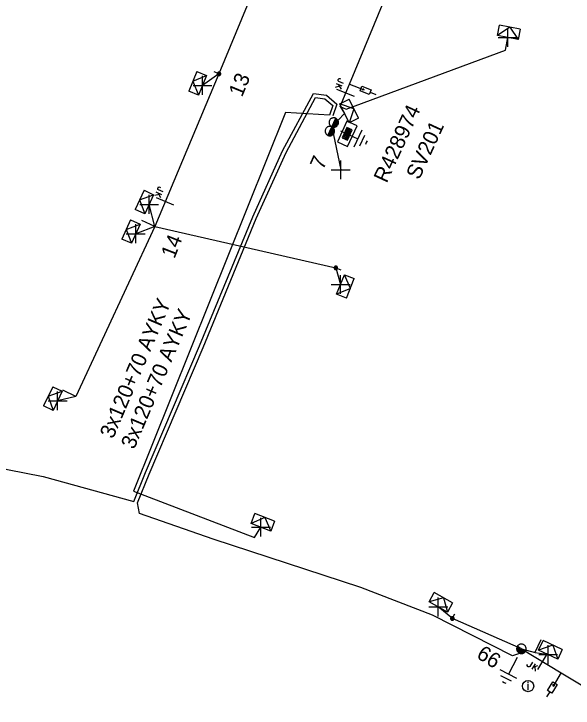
# Model space of a CAD drawing. Extents: x -540247 to -537390, y -1183890 to -1180355.
# Drawn here: x -537727.87 to -537690.84, y -1180542.13 to -1180496.15 of the extents above; entities that cross this region are included whole.
import ezdxf

# ---------------------------------------------------------------- set-up
doc = ezdxf.new("R2010")
doc.units = 0
for name, color, linetype in [('Vrstva 1', 7, 'Continuous'), ('Vrstva 10', 7, 'Continuous'), ('Vrstva 13', 7, 'Continuous'), ('Vrstva 14', 7, 'Continuous'), ('Vrstva 15', 7, 'Continuous'), ('Vrstva 16', 7, 'Continuous'), ('Vrstva 18', 7, 'Continuous'), ('Vrstva 2', 7, 'Continuous'), ('Vrstva 28', 7, 'Continuous'), ('Vrstva 29', 7, 'Continuous'), ('Vrstva 30', 7, 'Continuous'), ('Vrstva 31', 7, 'Continuous'), ('Vrstva 34', 7, 'Continuous'), ('Vrstva 36', 7, 'Continuous'), ('Vrstva 4', 7, 'Continuous'), ('Vrstva 5', 7, 'Continuous'), ('Vrstva 50', 7, 'Continuous'), ('Vrstva 52', 7, 'Continuous'), ('Vrstva 54', 7, 'Continuous'), ('Vrstva 6', 7, 'Continuous'), ('Vrstva 8', 7, 'Continuous'), ('Vrstva 9', 7, 'Continuous')]:
    doc.layers.add(name, color=color, linetype=linetype)

# ---------------------------------------------------------------- blocks, each defined once
blk = doc.blocks.new('NN440')
at = {"layer": 'Vrstva 2'}
for points in [[(0.631, -0.004), (0.627, 0.062), (0.617, 0.127), (0.6, 0.191), (0.577, 0.252), (0.547, 0.311), (0.511, 0.366), (0.469, 0.417), (0.423, 0.464), (0.371, 0.505), (0.316, 0.542), (0.257, 0.571), (0.196, 0.595), (0.132, 0.612), (0.067, 0.622), (0.001, 0.626), (-0.065, 0.622), (-0.13, 0.612), (-0.194, 0.595), (-0.255, 0.571), (-0.314, 0.542), (-0.369, 0.505), (-0.42, 0.464), (-0.467, 0.417), (-0.509, 0.366), (-0.544, 0.311), (-0.574, 0.252), (-0.598, 0.191), (-0.615, 0.127), (-0.626, 0.062), (-0.629, -0.004), (-0.626, -0.07), (-0.615, -0.135), (-0.598, -0.199), (-0.574, -0.26), (-0.544, -0.319), (-0.509, -0.374), (-0.467, -0.426), (-0.42, -0.472), (-0.369, -0.514), (-0.314, -0.55), (-0.255, -0.58), (-0.194, -0.603), (-0.13, -0.62), (-0.065, -0.631), (0.001, -0.634), (0.067, -0.631), (0.132, -0.62), (0.196, -0.603), (0.257, -0.58), (0.316, -0.55), (0.371, -0.514), (0.423, -0.472), (0.469, -0.426), (0.511, -0.374), (0.547, -0.319), (0.577, -0.26), (0.6, -0.199), (0.617, -0.135), (0.627, -0.07), (0.631, -0.004)], [(-0.631, 0), (0.629, 0)], [(-0.601, -0.177), (0.57, -0.177)], [(-0.513, -0.325), (0.501, -0.325)], [(-0.375, -0.473), (0.353, -0.473)]]:
    blk.add_lwpolyline(points, dxfattribs=at)
blk = doc.blocks.new('NN450')
at = {"layer": 'Vrstva 2'}
for points in [[(0, 0), (-0.003, 0.065), (-0.013, 0.13), (-0.031, 0.193), (-0.054, 0.254), (-0.084, 0.312), (-0.119, 0.367), (-0.161, 0.418), (-0.207, 0.464), (-0.258, 0.505), (-0.313, 0.541), (-0.371, 0.571), (-0.432, 0.594), (-0.495, 0.611), (-0.559, 0.621), (-0.625, 0.625), (-0.69, 0.621), (-0.755, 0.611), (-0.818, 0.594), (-0.879, 0.571), (-0.938, 0.541), (-0.992, 0.505), (-1.043, 0.464), (-1.089, 0.418), (-1.13, 0.367), (-1.166, 0.312), (-1.196, 0.254), (-1.219, 0.193), (-1.236, 0.13), (-1.246, 0.065), (-1.25, 0), (-1.246, -0.066), (-1.236, -0.13), (-1.219, -0.193), (-1.196, -0.255), (-1.166, -0.313), (-1.13, -0.368), (-1.089, -0.419), (-1.043, -0.465), (-0.992, -0.506), (-0.937, -0.542), (-0.879, -0.571), (-0.818, -0.595), (-0.755, -0.612), (-0.69, -0.622), (-0.625, -0.625), (-0.559, -0.622), (-0.495, -0.612), (-0.432, -0.595), (-0.37, -0.571), (-0.312, -0.542), (-0.258, -0.506), (-0.207, -0.465), (-0.161, -0.419), (-0.119, -0.368), (-0.084, -0.313), (-0.054, -0.254), (-0.031, -0.193), (-0.013, -0.13), (-0.003, -0.066), (0, 0)], [(1.25, 0), (1.247, 0.065), (1.237, 0.13), (1.219, 0.193), (1.196, 0.254), (1.166, 0.312), (1.131, 0.367), (1.089, 0.418), (1.043, 0.464), (0.992, 0.505), (0.937, 0.541), (0.879, 0.571), (0.818, 0.594), (0.755, 0.611), (0.691, 0.621), (0.625, 0.625), (0.56, 0.621), (0.495, 0.611), (0.432, 0.594), (0.371, 0.571), (0.312, 0.541), (0.258, 0.505), (0.207, 0.464), (0.161, 0.418), (0.12, 0.367), (0.084, 0.312), (0.054, 0.254), (0.031, 0.193), (0.014, 0.13), (0.004, 0.065), (0, 0), (0.004, -0.066), (0.014, -0.13), (0.031, -0.193), (0.054, -0.255), (0.084, -0.313), (0.12, -0.368), (0.161, -0.419), (0.207, -0.465), (0.258, -0.506), (0.313, -0.542), (0.371, -0.571), (0.432, -0.595), (0.495, -0.612), (0.56, -0.622), (0.625, -0.625), (0.691, -0.622), (0.755, -0.612), (0.818, -0.595), (0.88, -0.571), (0.938, -0.542), (0.992, -0.506), (1.043, -0.465), (1.089, -0.419), (1.131, -0.368), (1.166, -0.313), (1.196, -0.254), (1.219, -0.193), (1.237, -0.13), (1.247, -0.066), (1.25, 0)], [(-1.25, 0), (1.25, 0)], [(-1.23, -0.158), (-0.02, -0.158)], [(-1.161, -0.315), (-0.088, -0.315)], [(-1.033, -0.473), (-0.216, -0.473)], [(0.02, -0.158), (1.23, -0.158)], [(0.089, -0.315), (1.162, -0.315)], [(0.217, -0.473), (1.034, -0.473)]]:
    blk.add_lwpolyline(points, dxfattribs=at)
blk = doc.blocks.new('NN840')
at = {"layer": 'Vrstva 15'}
for points in [[(0.003, 0.619), (0.003, -0.631)], [(-0.538, -0.385), (-0.538, -0.71)], [(-0.332, -0.385), (-0.332, -0.798)], [(-0.332, -0.641), (-0.125, -0.385)], [(-0.745, -0.71), (-0.745, -0.66)], [(-0.73, -0.764), (-0.745, -0.71)], [(-0.657, -0.798), (-0.73, -0.764)], [(-0.627, -0.798), (-0.657, -0.798)], [(-0.558, -0.764), (-0.627, -0.798)], [(-0.538, -0.71), (-0.558, -0.764)], [(-0.263, -0.557), (-0.091, -0.798)]]:
    blk.add_lwpolyline(points, dxfattribs=at)
blk = doc.blocks.new('NN770')
at = {"layer": 'Vrstva 10'}
for p, q in [((0.002, 0.187), (0.002, 0.263)), ((0.002, -0.276), (0.002, 0.111))]:
    blk.add_line(p, q, dxfattribs=at)
blk.add_circle((0, -0.008), 0.375, dxfattribs=at)
blk = doc.blocks.new('NN800')
at = {"layer": 'Vrstva 1'}
for points in [[(-0.442, 0.442), (0.442, -0.442)], [(-0.442, -0.442), (0.442, 0.442)]]:
    blk.add_lwpolyline(points, dxfattribs=at)
blk = doc.blocks.new('NN820')
at = {"layer": 'Vrstva 13'}
for points in [[(-0.003, 0.004), (-0.003, -1.049)], [(-0.165, -0.813), (0.165, -0.813)], [(-0.165, -1.473), (-0.165, -0.813)], [(0.165, -0.813), (0.165, -1.473)], [(-0.003, -1.049), (-0.062, -0.926)], [(-0.003, -1.049), (0.057, -0.926)], [(0.165, -1.473), (-0.165, -1.473)], [(-0.003, -1.473), (-0.003, -1.871)]]:
    blk.add_lwpolyline(points, dxfattribs=at)
blk = doc.blocks.new('NN620')
at = {"layer": 'Vrstva 8'}
for points in [[(0.752, 0.004), (-0.748, 0.004)], [(-0.748, 0.004), (-0.748, -0.746)], [(0.752, -0.746), (0.752, 0.004)], [(0.368, -0.18), (-0.376, -0.18)], [(-0.376, -0.18), (-0.376, -0.558)], [(0.321, -0.227), (-0.329, -0.227)], [(-0.329, -0.227), (-0.329, -0.51)], [(0.274, -0.274), (-0.281, -0.274)], [(-0.281, -0.274), (-0.281, -0.463)], [(0.227, -0.321), (-0.234, -0.321)], [(-0.234, -0.321), (-0.234, -0.416)], [(-0.234, -0.416), (0.227, -0.416)], [(-0.193, -0.369), (0.185, -0.369)], [(0.227, -0.416), (0.227, -0.321)], [(0.274, -0.463), (0.274, -0.274)], [(0.321, -0.51), (0.321, -0.227)], [(0.368, -0.558), (0.368, -0.18)], [(-0.748, -0.746), (0.752, -0.746)], [(-0.376, -0.558), (0.368, -0.558)], [(-0.329, -0.51), (0.321, -0.51)], [(-0.281, -0.463), (0.274, -0.463)]]:
    blk.add_lwpolyline(points, dxfattribs=at)
blk = doc.blocks.new('NN630')
at = {"layer": 'Vrstva 9'}
for points in [[(-0.003, -0.7), (-0.703, 0)], [(-0.703, -0.7), (-0.703, 0), (0.697, 0), (0.697, -0.7)], [(-0.003, -0.7), (0.697, 0)], [(-0.703, -0.7), (0.697, -0.7)]]:
    blk.add_lwpolyline(points, dxfattribs=at)
blk = doc.blocks.new('NN810')
at = {"layer": 'Vrstva 14'}
for points in [[(0.004, -0.64), (0.004, -1.89)], [(0.629, -1.89), (-0.621, -1.89)], [(0.388, -2.2), (-0.399, -2.2)], [(0.004, -2.515), (-0.124, -2.515)], [(0.137, -2.515), (0.004, -2.515)]]:
    blk.add_lwpolyline(points, dxfattribs=at)
blk = doc.blocks.new('NN500')
at = {"layer": 'Vrstva 2'}
for points in [[(-0.001, -0.235), (0.023, -0.234), (0.048, -0.23), (0.071, -0.224), (0.094, -0.215), (0.116, -0.204), (0.137, -0.191), (0.156, -0.175), (0.173, -0.158), (0.189, -0.139), (0.202, -0.118), (0.213, -0.096), (0.222, -0.073), (0.229, -0.049), (0.232, -0.025), (0.234, 0), (0.232, 0.024), (0.229, 0.048), (0.222, 0.072), (0.213, 0.095), (0.202, 0.117), (0.189, 0.138), (0.173, 0.157), (0.156, 0.174), (0.137, 0.19), (0.116, 0.203), (0.094, 0.214), (0.071, 0.223), (0.048, 0.229), (0.023, 0.233), (-0.001, 0.235), (-0.026, 0.233), (-0.05, 0.229), (-0.074, 0.223), (-0.097, 0.214), (-0.119, 0.203), (-0.139, 0.19), (-0.158, 0.174), (-0.176, 0.157), (-0.191, 0.138), (-0.205, 0.117), (-0.216, 0.095), (-0.225, 0.072), (-0.231, 0.048), (-0.235, 0.024), (-0.236, 0), (-0.235, -0.025), (-0.231, -0.049), (-0.225, -0.073), (-0.216, -0.096), (-0.205, -0.118), (-0.191, -0.139), (-0.176, -0.158), (-0.158, -0.175), (-0.139, -0.191), (-0.119, -0.204), (-0.097, -0.215), (-0.074, -0.224), (-0.05, -0.23), (-0.026, -0.234), (-0.001, -0.235)], [(-0.001, -0.235), (0.023, -0.234), (0.048, -0.23), (0.071, -0.224), (0.094, -0.215), (0.116, -0.204), (0.137, -0.191), (0.156, -0.175), (0.173, -0.158), (0.189, -0.139), (0.202, -0.118), (0.213, -0.096), (0.222, -0.073), (0.229, -0.049), (0.232, -0.025), (0.234, 0), (0.232, 0.024), (0.229, 0.048), (0.222, 0.072), (0.213, 0.095), (0.202, 0.117), (0.189, 0.138), (0.173, 0.157), (0.156, 0.174), (0.137, 0.19), (0.116, 0.203), (0.094, 0.214), (0.071, 0.223), (0.048, 0.229), (0.023, 0.233), (-0.001, 0.235), (-0.026, 0.233), (-0.05, 0.229), (-0.074, 0.223), (-0.097, 0.214), (-0.119, 0.203), (-0.139, 0.19), (-0.158, 0.174), (-0.176, 0.157), (-0.191, 0.138), (-0.205, 0.117), (-0.216, 0.095), (-0.225, 0.072), (-0.231, 0.048), (-0.235, 0.024), (-0.236, 0), (-0.235, -0.025), (-0.231, -0.049), (-0.225, -0.073), (-0.216, -0.096), (-0.205, -0.118), (-0.191, -0.139), (-0.176, -0.158), (-0.158, -0.175), (-0.139, -0.191), (-0.119, -0.204), (-0.097, -0.215), (-0.074, -0.224), (-0.05, -0.23), (-0.026, -0.234), (-0.001, -0.235)], [(-0.001, -0.206), (0.02, -0.205), (0.041, -0.201), (0.062, -0.196), (0.082, -0.188), (0.101, -0.178), (0.12, -0.167), (0.136, -0.153), (0.151, -0.138), (0.165, -0.121), (0.177, -0.103), (0.186, -0.084), (0.194, -0.064), (0.2, -0.043), (0.203, -0.022), (0.204, 0), (0.203, 0.021), (0.2, 0.042), (0.194, 0.063), (0.186, 0.083), (0.177, 0.102), (0.165, 0.12), (0.151, 0.137), (0.136, 0.152), (0.12, 0.166), (0.101, 0.177), (0.082, 0.187), (0.062, 0.195), (0.041, 0.2), (0.02, 0.204), (-0.001, 0.205), (-0.023, 0.204), (-0.044, 0.2), (-0.065, 0.195), (-0.085, 0.187), (-0.104, 0.177), (-0.122, 0.166), (-0.139, 0.152), (-0.154, 0.137), (-0.167, 0.12), (-0.179, 0.102), (-0.189, 0.083), (-0.197, 0.063), (-0.202, 0.042), (-0.205, 0.021), (-0.207, 0), (-0.205, -0.022), (-0.202, -0.043), (-0.197, -0.064), (-0.189, -0.084), (-0.179, -0.103), (-0.167, -0.121), (-0.154, -0.138), (-0.139, -0.153), (-0.122, -0.167), (-0.104, -0.178), (-0.085, -0.188), (-0.065, -0.196), (-0.044, -0.201), (-0.023, -0.205), (-0.001, -0.206)], [(-0.001, -0.176), (0.017, -0.175), (0.035, -0.172), (0.053, -0.168), (0.07, -0.161), (0.087, -0.153), (0.102, -0.143), (0.116, -0.131), (0.129, -0.118), (0.141, -0.104), (0.151, -0.088), (0.159, -0.072), (0.166, -0.055), (0.171, -0.037), (0.174, -0.019), (0.175, 0), (0.174, 0.018), (0.171, 0.036), (0.166, 0.054), (0.159, 0.071), (0.151, 0.087), (0.141, 0.103), (0.129, 0.117), (0.116, 0.13), (0.102, 0.142), (0.087, 0.152), (0.07, 0.16), (0.053, 0.167), (0.035, 0.172), (0.017, 0.174), (-0.001, 0.175), (-0.02, 0.174), (-0.038, 0.172), (-0.056, 0.167), (-0.073, 0.16), (-0.089, 0.152), (-0.105, 0.142), (-0.119, 0.13), (-0.132, 0.117), (-0.143, 0.103), (-0.153, 0.087), (-0.162, 0.071), (-0.168, 0.054), (-0.173, 0.036), (-0.176, 0.018), (-0.177, 0), (-0.176, -0.019), (-0.173, -0.037), (-0.168, -0.055), (-0.162, -0.072), (-0.153, -0.088), (-0.143, -0.104), (-0.132, -0.118), (-0.119, -0.131), (-0.105, -0.143), (-0.089, -0.153), (-0.073, -0.161), (-0.056, -0.168), (-0.038, -0.172), (-0.02, -0.175), (-0.001, -0.176)], [(-0.001, -0.147), (0.014, -0.146), (0.029, -0.143), (0.044, -0.139), (0.058, -0.134), (0.072, -0.127), (0.085, -0.119), (0.097, -0.109), (0.107, -0.098), (0.117, -0.086), (0.125, -0.073), (0.132, -0.06), (0.138, -0.046), (0.142, -0.031), (0.144, -0.016), (0.145, 0), (0.144, 0.015), (0.142, 0.03), (0.138, 0.045), (0.132, 0.059), (0.125, 0.073), (0.117, 0.086), (0.107, 0.097), (0.097, 0.108), (0.085, 0.118), (0.072, 0.126), (0.058, 0.133), (0.044, 0.139), (0.029, 0.143), (0.014, 0.145), (-0.001, 0.146), (-0.017, 0.145), (-0.032, 0.143), (-0.046, 0.139), (-0.061, 0.133), (-0.074, 0.126), (-0.087, 0.118), (-0.099, 0.108), (-0.11, 0.097), (-0.119, 0.086), (-0.128, 0.073), (-0.135, 0.059), (-0.14, 0.045), (-0.144, 0.03), (-0.147, 0.015), (-0.147, 0), (-0.147, -0.016), (-0.144, -0.031), (-0.14, -0.046), (-0.135, -0.06), (-0.128, -0.073), (-0.119, -0.086), (-0.11, -0.098), (-0.099, -0.109), (-0.087, -0.119), (-0.074, -0.127), (-0.061, -0.134), (-0.046, -0.139), (-0.032, -0.143), (-0.017, -0.146), (-0.001, -0.147)], [(-0.001, -0.117), (0.011, -0.116), (0.023, -0.114), (0.035, -0.111), (0.046, -0.107), (0.057, -0.101), (0.067, -0.095), (0.077, -0.087), (0.085, -0.078), (0.093, -0.069), (0.1, -0.059), (0.105, -0.048), (0.11, -0.036), (0.113, -0.025), (0.115, -0.013), (0.115, 0), (0.115, 0.012), (0.113, 0.024), (0.11, 0.036), (0.105, 0.047), (0.1, 0.058), (0.093, 0.068), (0.085, 0.078), (0.077, 0.086), (0.067, 0.094), (0.057, 0.101), (0.046, 0.106), (0.035, 0.11), (0.023, 0.114), (0.011, 0.116), (-0.001, 0.116), (-0.013, 0.116), (-0.025, 0.114), (-0.037, 0.11), (-0.049, 0.106), (-0.059, 0.101), (-0.07, 0.094), (-0.079, 0.086), (-0.088, 0.078), (-0.096, 0.068), (-0.102, 0.058), (-0.108, 0.047), (-0.112, 0.036), (-0.115, 0.024), (-0.117, 0.012), (-0.118, 0), (-0.117, -0.013), (-0.115, -0.025), (-0.112, -0.036), (-0.108, -0.048), (-0.102, -0.059), (-0.096, -0.069), (-0.088, -0.078), (-0.079, -0.087), (-0.07, -0.095), (-0.059, -0.101), (-0.049, -0.107), (-0.037, -0.111), (-0.025, -0.114), (-0.013, -0.116), (-0.001, -0.117)], [(-0.001, -0.087), (0.008, -0.087), (0.017, -0.085), (0.026, -0.083), (0.034, -0.08), (0.042, -0.076), (0.05, -0.071), (0.057, -0.065), (0.063, -0.059), (0.069, -0.051), (0.074, -0.044), (0.078, -0.036), (0.081, -0.027), (0.084, -0.019), (0.085, -0.01), (0.086, 0), (0.085, 0.009), (0.084, 0.018), (0.081, 0.026), (0.078, 0.035), (0.074, 0.043), (0.069, 0.051), (0.063, 0.058), (0.057, 0.064), (0.05, 0.07), (0.042, 0.075), (0.034, 0.079), (0.026, 0.082), (0.017, 0.085), (0.008, 0.086), (-0.001, 0.087), (-0.01, 0.086), (-0.019, 0.085), (-0.028, 0.082), (-0.037, 0.079), (-0.045, 0.075), (-0.052, 0.07), (-0.059, 0.064), (-0.066, 0.058), (-0.072, 0.051), (-0.077, 0.043), (-0.081, 0.035), (-0.084, 0.026), (-0.086, 0.018), (-0.088, 0.009), (-0.088, 0), (-0.088, -0.01), (-0.086, -0.019), (-0.084, -0.027), (-0.081, -0.036), (-0.077, -0.044), (-0.072, -0.052), (-0.066, -0.059), (-0.059, -0.065), (-0.052, -0.071), (-0.045, -0.076), (-0.037, -0.08), (-0.028, -0.083), (-0.019, -0.085), (-0.01, -0.087), (-0.001, -0.087)], [(-0.001, -0.058), (0.005, -0.057), (0.011, -0.056), (0.016, -0.055), (0.022, -0.053), (0.027, -0.05), (0.032, -0.047), (0.037, -0.043), (0.041, -0.039), (0.045, -0.034), (0.048, -0.029), (0.051, -0.024), (0.053, -0.018), (0.055, -0.012), (0.056, -0.006), (0.056, 0), (0.056, 0.006), (0.055, 0.011), (0.053, 0.017), (0.051, 0.023), (0.048, 0.028), (0.045, 0.033), (0.041, 0.038), (0.037, 0.042), (0.032, 0.046), (0.027, 0.049), (0.022, 0.052), (0.016, 0.054), (0.011, 0.056), (0.005, 0.057), (-0.001, 0.057), (-0.007, 0.057), (-0.013, 0.056), (-0.019, 0.054), (-0.025, 0.052), (-0.03, 0.049), (-0.035, 0.046), (-0.04, 0.042), (-0.044, 0.038), (-0.048, 0.033), (-0.051, 0.028), (-0.054, 0.023), (-0.056, 0.017), (-0.057, 0.011), (-0.058, 0.006), (-0.059, 0), (-0.058, -0.006), (-0.057, -0.012), (-0.056, -0.018), (-0.054, -0.024), (-0.051, -0.029), (-0.048, -0.034), (-0.044, -0.039), (-0.04, -0.043), (-0.035, -0.047), (-0.03, -0.05), (-0.025, -0.053), (-0.019, -0.055), (-0.013, -0.056), (-0.007, -0.057), (-0.001, -0.058)], [(-0.001, -0.028), (0.002, -0.028), (0.005, -0.028), (0.007, -0.027), (0.01, -0.026), (0.013, -0.024), (0.015, -0.023), (0.017, -0.021), (0.019, -0.019), (0.021, -0.017), (0.023, -0.014), (0.024, -0.012), (0.025, -0.009), (0.026, -0.006), (0.026, -0.003), (0.027, 0), (0.026, 0.002), (0.026, 0.005), (0.025, 0.008), (0.024, 0.011), (0.023, 0.013), (0.021, 0.016), (0.019, 0.018), (0.017, 0.02), (0.015, 0.022), (0.013, 0.024), (0.01, 0.025), (0.007, 0.026), (0.005, 0.027), (0.002, 0.027), (-0.001, 0.027), (-0.004, 0.027), (-0.007, 0.027), (-0.01, 0.026), (-0.012, 0.025), (-0.015, 0.024), (-0.018, 0.022), (-0.02, 0.02), (-0.022, 0.018), (-0.024, 0.016), (-0.025, 0.013), (-0.027, 0.011), (-0.028, 0.008), (-0.028, 0.005), (-0.029, 0.002), (-0.029, 0), (-0.029, -0.003), (-0.028, -0.006), (-0.028, -0.009), (-0.027, -0.012), (-0.025, -0.014), (-0.024, -0.017), (-0.022, -0.019), (-0.02, -0.021), (-0.018, -0.023), (-0.015, -0.024), (-0.012, -0.026), (-0.01, -0.027), (-0.007, -0.028), (-0.004, -0.028), (-0.001, -0.028)], [(0.234, 0), (0.704, 0)]]:
    blk.add_lwpolyline(points, dxfattribs=at)
blk = doc.blocks.new('NN510')
at = {"layer": 'Vrstva 2'}
blk.add_lwpolyline([(0.001, 0.002), (0.001, 0.939)], dxfattribs=at)

msp = doc.modelspace()

# ---------------------------------------------------------------- linework, layer by layer
at = {"layer": 'Vrstva 4'}
msp.add_lwpolyline([(-537718.536, -1180510.223), (-537706.55, -1180512.97), (-537706.235, -1180514.068)], dxfattribs=at)
at = {"layer": 'Vrstva 5'}
for points in [[(-537734.68, -1180524.19), (-537734.74, -1180524.45), (-537732.42, -1180525.38), (-537728.3, -1180526.32), (-537725.94, -1180526.78), (-537719.916, -1180528.443), (-537719.145, -1180526.532), (-537715.575, -1180518.142), (-537712.055, -1180509.59), (-537710.072, -1180505.214), (-537708.029, -1180501.425), (-537707.177, -1180501.531), (-537706.489, -1180502.117), (-537706.751, -1180502.897)], [(-537694.259, -1180538.2), (-537694.383, -1180538.509), (-537694.85, -1180538.67), (-537700.14, -1180535.98), (-537704.89, -1180534.15), (-537714.67, -1180530.95), (-537719.56, -1180529.24), (-537719.684, -1180528.537), (-537718.915, -1180526.628), (-537715.345, -1180518.238), (-537711.825, -1180509.69), (-537709.848, -1180505.326), (-537707.891, -1180501.695), (-537707.283, -1180501.769), (-537706.751, -1180502.223), (-537706.972, -1180502.847)]]:
    msp.add_lwpolyline(points, dxfattribs=at)
at = {"layer": 'Vrstva 50'}
for points in [[(-537695.509, -1180475.222), (-537708.786, -1180486.772), (-537714.289, -1180500.117), (-537718.536, -1180510.223)], [(-537706.255, -1180502.27), (-537705.642, -1180500.791), (-537695.184, -1180475.522)], [(-537694.26, -1180538.199), (-537691.624, -1180539.786), (-537675.507, -1180549.486), (-537663.756, -1180552.682), (-537651.753, -1180559.088), (-537616.15, -1180576.16), (-537591.135, -1180593.384), (-537584.357, -1180598.332)]]:
    msp.add_lwpolyline(points, dxfattribs=at)
at = {"layer": 'Vrstva 52'}
for points in [[(-537706.255, -1180502.27), (-537705.862, -1180502.457), (-537705.264, -1180502.227), (-537695.308, -1180498.547), (-537695.168, -1180497.706)], [(-537706.255, -1180502.27), (-537705.987, -1180502.739), (-537706.815, -1180503.624), (-537706.223, -1180506.478)], [(-537706.972, -1180502.847), (-537709.876, -1180502.687), (-537719.944, -1180527.767), (-537711.939, -1180530.834), (-537711.509, -1180530.148)]]:
    msp.add_lwpolyline(points, dxfattribs=at)
at = {"layer": 'Vrstva 54'}
for points in [[(-537714.289, -1180500.117), (-537715.376, -1180500.882)], [(-537718.536, -1180510.223), (-537718.913, -1180508.765)], [(-537718.536, -1180510.223), (-537719.799, -1180510.708)], [(-537694.26, -1180538.2), (-537693.348, -1180538.435), (-537692.489, -1180538.584)]]:
    msp.add_lwpolyline(points, dxfattribs=at)
at = {"layer": 'Vrstva 8'}
for points in [[(-537718.536, -1180510.223), (-537723.775, -1180521.485), (-537724.975, -1180521.779)], [(-537694.26, -1180538.2), (-537698.832, -1180536.193), (-537699.768, -1180535.429)]]:
    msp.add_lwpolyline(points, dxfattribs=at)

# ---------------------------------------------------------------- block references
at = {"layer": 'Vrstva 13'}
for name, p, xscale, yscale, rotation in [('NN500', (-537714.289, -1180500.117), 0.5000000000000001, 0.5, 157.57999991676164), ('NN450', (-537706.816, -1180503.625), 0.5, 0.49999999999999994, 65.39917218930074), ('NN500', (-537706.55, -1180512.97), 0.49999999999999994, 0.5000000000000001, -21.98999987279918), ('NN500', (-537698.832, -1180536.193), 0.5, 0.5, 61.31899999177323), ('NN440', (-537694.26, -1180538.199), 0.5, 0.5, -32.04825282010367)]:
    msp.add_blockref(name, p, dxfattribs=dict(at, xscale=xscale, yscale=yscale, rotation=rotation))
for p, rotation in [((-537718.536, -1180510.224), 64.97272221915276), ((-537723.774, -1180521.486), 64.16566394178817), ((-537693.349, -1180538.436), -25.18302502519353)]:
    msp.add_blockref('NN510', p, dxfattribs=dict(at, rotation=rotation))
at = {"layer": 'Vrstva 15'}
for p, rotation in [((-537706.815, -1180503.624), 65.19926120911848), ((-537694.261, -1180538.2), -26.91949160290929)]:
    msp.add_blockref('NN810', p, dxfattribs=dict(at, rotation=rotation))
at = {"layer": 'Vrstva 16'}
for p, rotation in [((-537705.642, -1180500.791), 68.49706113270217), ((-537691.624, -1180539.786), -31.042769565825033)]:
    msp.add_blockref('NN820', p, dxfattribs=dict(at, rotation=rotation))
at = {"layer": 'Vrstva 18'}
for p, rotation in [((-537705.891, -1180501.39), -111.5029389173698), ((-537717.845, -1180508.578), -112.79435559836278), ((-537692.87, -1180539.036), -31.049908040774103)]:
    msp.add_blockref('NN840', p, dxfattribs=dict(at, rotation=rotation))
at = {"layer": 'Vrstva 28', "rotation": 65.32699999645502}
msp.add_blockref('NN620', (-537706.133, -1180503.937), dxfattribs=at)
at = {"layer": 'Vrstva 31'}
for p, rotation in [((-537695.168, -1180497.706), 168.68557226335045), ((-537715.376, -1180500.882), -112.42006109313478), ((-537705.987, -1180502.739), 116.28159717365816), ((-537718.913, -1180508.765), -115.02727778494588), ((-537719.799, -1180510.708), -114.1805888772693), ((-537706.235, -1180514.068), 68.01026113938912), ((-537724.975, -1180521.779), -115.83433617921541), ((-537711.509, -1180530.148), 158.978883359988), ((-537699.768, -1180535.429), 151.31901392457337), ((-537692.489, -1180538.584), 154.81697500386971)]:
    msp.add_blockref('NN630', p, dxfattribs=dict(at, rotation=rotation))
at = {"layer": 'Vrstva 34'}
for p, rotation in [((-537695.168, -1180497.706), 44.99999995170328), ((-537715.376, -1180500.882), 45), ((-537706.223, -1180506.478), 45), ((-537718.913, -1180508.765), 44.99999995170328), ((-537719.799, -1180510.708), 45), ((-537706.235, -1180514.068), 45), ((-537724.975, -1180521.779), 45), ((-537711.509, -1180530.148), 45), ((-537699.768, -1180535.429), 45), ((-537692.489, -1180538.584), 44.99999995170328)]:
    msp.add_blockref('NN800', p, dxfattribs=dict(at, rotation=rotation))
at = {"layer": 'Vrstva 36'}
msp.add_blockref('NN770', (-537693.82, -1180540.662), dxfattribs=at)

# ---------------------------------------------------------------- texts
at = {"layer": 'Vrstva 14'}
for s, rotation, p in [('13', 67.484, (-537712.765, -1180501.706)), ('7', 66.193, (-537707.391, -1180506.524)), ('14', 68.448, (-537717.239, -1180512.406)), ('66', 327.884, (-537697.298, -1180538.761))]:
    msp.add_text(s, height=1, rotation=rotation, dxfattribs=at).set_placement(p)
at = {"layer": 'Vrstva 29'}
msp.add_text('R428974', height=1, rotation=65.327, dxfattribs=at).set_placement((-537703.182, -1180507.4))
at = {"layer": 'Vrstva 30'}
msp.add_text('SV201', height=1, rotation=65.327, dxfattribs=at).set_placement((-537701.033, -1180507.185))
at = {"layer": 'Vrstva 6'}
for p in [(-537721.302, -1180524.338), (-537719.905, -1180525.037)]:
    msp.add_text('3x120+70 AYKY', height=1, rotation=66.95, dxfattribs=at).set_placement(p)

doc.saveas('drawing.dxf')
